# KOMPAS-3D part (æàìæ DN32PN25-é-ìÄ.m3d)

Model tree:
1. Объединить компоненты:1  (labels: СЕНС DN32PN25-В-НО)

Referenced files in D:\Савин\!СЕНСОР\3D для заказчика\!Новый перечень\СЕНС\6. СЕНС-В-НО\DN32\: СЕНС DN32PN25-В-НО.a3d
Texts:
  СЕНС DN32PN25-В-НО
  ООО НПП Сенсор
